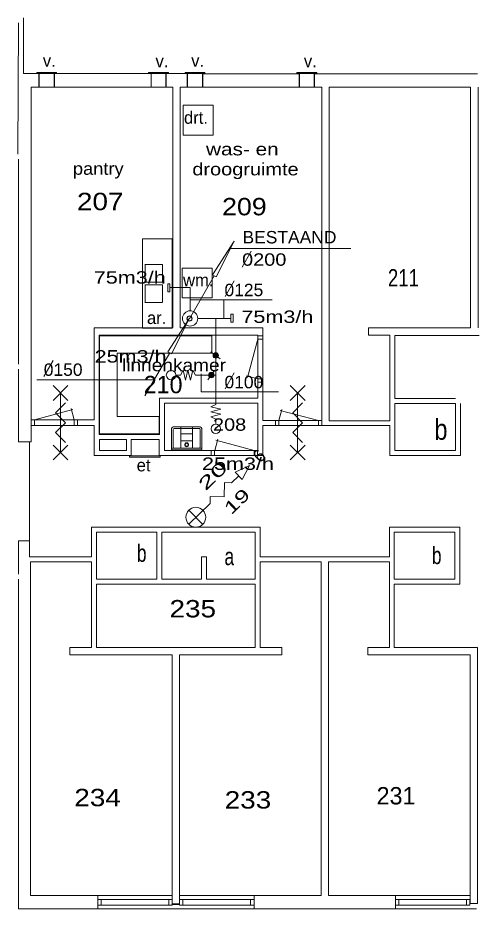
# Model space of a CAD drawing. Extents: x 295824 to 414724, y 24924 to 109024.
# Drawn here: x 361055 to 370346, y 62517 to 80477 of the extents above; entities that cross this region are included whole.
import ezdxf
from ezdxf.enums import TextEntityAlignment as Align

# ---------------------------------------------------------------- set-up
doc = ezdxf.new("R2010")
doc.units = 0
doc.header["$LTSCALE"] = 100
for name, color, linetype, lineweight in [('1', 7, 'Continuous', 13), ('24', 7, 'Continuous', 13), ('61', 7, 'Continuous', 13)]:
    doc.layers.add(name, color=color, linetype=linetype, lineweight=lineweight)

msp = doc.modelspace()

# ---------------------------------------------------------------- hatches: boundary and pattern name
at = {"layer": '24'}
for points in [[(364986.6, 73674.2, 1), (365095.2, 73674.2, 1)], [(364951.3, 73331.6, 1), (364951.3, 73223, 1)]]:
    msp.add_hatch(color=256, dxfattribs=at).paths.add_polyline_path(points)

# ---------------------------------------------------------------- linework, layer by layer
at = {"layer": '1'}
for p, q in [((364511.7, 74414.9), (365011.7, 75280.9)), ((363614.5, 72863.1), (364114.5, 73729.1))]:
    msp.add_line(p, q, dxfattribs=at)
for points in [[(365411.7, 75973.9), (365047.7, 75259.9), (364975.7, 75301.9)], [(364514.5, 74422.1), (364150.5, 73708.1), (364078.5, 73750.1)]]:
    msp.add_lwpolyline(points, close=True, dxfattribs=at)
msp.add_lwpolyline([(364526.2, 74579.8), (364526.2, 75046.4), (364118.1, 75046.4)], dxfattribs=at)
for centre in [(364511.6, 74414.6), (364514.5, 74421.8)]:
    msp.add_circle(centre, 50, dxfattribs=at)
at = {"layer": '24'}
for p, q in [((365322.8, 75827.7), (367762.3, 75827.7)), ((365757.4, 75774.7), (365573.1, 75455.4)), ((365413.1, 75178.3), (365228.7, 74859)), ((364526.2, 74795.5), (366180.1, 74795.5)), ((365205.3, 74433.6), (365205.3, 74795.5)), ((364678.1, 74419.5), (365340.7, 74419.5)), ((365040.9, 72738.8), (365040.9, 74419.5)), ((365132.5, 73603.3), (364941, 73745)), ((361763.6, 73571.9), (361579.3, 73252.6)), ((364880.5, 73185.7), (365022.2, 73377.3)), ((365413.1, 73321.7), (365228.7, 73002.3)), ((361439.1, 73184.3), (363799.9, 73184.3)), ((364682.2, 73277.3), (365040.9, 73277.3))]:
    msp.add_line(p, q, dxfattribs=at)
for points in [[(364116.5, 75115.3), (364073, 75115.3), (364073, 74953), (364116.5, 74953)], [(365390.7, 74507), (365347.2, 74507), (365347.2, 74344.7), (365390.7, 74344.7)]]:
    msp.add_lwpolyline(points, close=True, dxfattribs=at)
for points in [[(364232.2, 73277.3), (364332.2, 73277.3), (364382.2, 73377.3), (364432.2, 73177.3), (364482.2, 73377.3), (364532.2, 73177.3), (364582.2, 73377.3), (364632.2, 73277.3), (364682.2, 73277.3)], [(364749.3, 73300.7), (364749.3, 72938.9), (366305.9, 72938.9)], [(365040.9, 72288.8), (365040.9, 72388.8), (364940.9, 72438.8), (365140.9, 72488.8), (364940.9, 72538.8), (365140.9, 72588.8), (364940.9, 72638.8), (365040.9, 72688.8), (365040.9, 72738.8)]]:
    msp.add_lwpolyline(points, dxfattribs=at)
for centre, radius in [((364524.6, 74419.5), 153.6), ((365040.9, 73674.2), 54.3), ((364140.5, 73277.3), 95), ((364951.3, 73277.3), 54.3), ((365040.9, 72197.1), 95)]:
    msp.add_circle(centre, radius, dxfattribs=at)
at = {"layer": '61'}
for p, q in [((361168.1, 80477.2), (361168.1, 79352.1)), ((361055.1, 77727.2), (361068.1, 80377.2)), ((361168.1, 79352.1), (364468.2, 79352.1)), ((361833.8, 79372.3), (361435.5, 79372.3)), ((361435.5, 79372.3), (361435.5, 79357.2)), ((361833.8, 79357.2), (361435.5, 79357.2)), ((361480.2, 79352.1), (361480.2, 79082.1)), ((361485.8, 79357.2), (361485.8, 79082.8)), ((361784.5, 79357.2), (361784.5, 79082.8)), ((361790.9, 79350.8), (361790.9, 79082.3)), ((361833.8, 79372.3), (361833.8, 79357.2)), ((364087.5, 79372.3), (363689.2, 79372.3)), ((363689.2, 79372.3), (363689.2, 79357.2)), ((364087.5, 79357.2), (363689.2, 79357.2)), ((363739.5, 79357.2), (363739.5, 79082.8)), ((364038.2, 79357.2), (364038.2, 79082.8)), ((364044.6, 79350.7), (364044.6, 79080.7)), ((364087.5, 79372.3), (364087.5, 79357.2)), ((364821.8, 79372.3), (364423.5, 79372.3)), ((364423.5, 79372.3), (364423.5, 79357.2)), ((364821.8, 79357.2), (364423.5, 79357.2)), ((364468.2, 79352.1), (364468.2, 79082.1)), ((364473.7, 79357.2), (364473.7, 79082.8)), ((364772.4, 79357.2), (364772.4, 79082.8)), ((364778.9, 79350.8), (364778.9, 79082.3)), ((364778.9, 79350.8), (366721.9, 79350.8)), ((364821.8, 79372.3), (364821.8, 79357.2)), ((367075.5, 79372.3), (366677.2, 79372.3)), ((366677.2, 79372.3), (366677.2, 79357.2)), ((367075.5, 79357.2), (366677.2, 79357.2)), ((366721.9, 79350.8), (366721.9, 79082.3)), ((366727.5, 79357.2), (366727.5, 79082.8)), ((367026.2, 79357.2), (367026.2, 79082.8)), ((367032.6, 79350.7), (370310.6, 79350.7)), ((367032.6, 79350.7), (367032.6, 79080.7)), ((367075.5, 79372.3), (367075.5, 79357.2)), ((361325.1, 71936.1), (361325.1, 79080.7)), ((361784.5, 79082.8), (361485.8, 79082.8)), ((361790.9, 79082.3), (361936.7, 79082.3)), ((363587.2, 79082.3), (363733.9, 79082.3)), ((364038.2, 79082.8), (363739.5, 79082.8)), ((364325.1, 79082.1), (364468.2, 79082.1)), ((364325.1, 74230.7), (364325.1, 79080.8)), ((367175.1, 79080.8), (364325.1, 79080.8)), ((364772.4, 79082.8), (364473.7, 79082.8)), ((364778.9, 79082.3), (364924.7, 79082.3)), ((366575.2, 79082.3), (366721.9, 79082.3)), ((367026.2, 79082.8), (366727.5, 79082.8)), ((367032.6, 79080.7), (367175.1, 79080.7)), ((367175.1, 72262), (367175.1, 79080.8)), ((370325.1, 79080.7), (370325.1, 74230.7)), ((361068.1, 77627.2), (361068.1, 73497.4)), ((363615.5, 75505.1), (363965.5, 75505.1)), ((363966.4, 75503.5), (363966.4, 75153.5)), ((363965.5, 75151), (363615.5, 75151)), ((363615.5, 75096.9), (363965.5, 75096.9)), ((363966.4, 75095.3), (363966.4, 74745.3)), ((363965.5, 74742.8), (363615.5, 74742.8)), ((362590.4, 74230.7), (362590.4, 72374.6)), ((364325.1, 74230.7), (365990.4, 74230.7)), ((362690.4, 72080.4), (362690.4, 74085.4)), ((365888.4, 74001.2), (365681.4, 73228.4)), ((365989.9, 74067.4), (365889, 74067.4)), ((365987.9, 74000.4), (365890.4, 74000.4)), ((365988.3, 74067.4), (365891.6, 74067.4)), ((368650.1, 72805.7), (368650.1, 74079.4)), ((370346.5, 74079.4), (368650.1, 74079.4)), ((365887.8, 73202.8), (365660.9, 73263.5)), ((365987.7, 73200.4), (365889, 73200.4)), ((365987.9, 73133.4), (365889, 73133.4)), ((362063.4, 73069.3), (361763.4, 72769.3)), ((361763.4, 73069.3), (362063.4, 72769.3)), ((361913.4, 71719.3), (361913.4, 72919.3)), ((366840.6, 73069.3), (366540.6, 72769.3)), ((366540.6, 73069.3), (366840.6, 72769.3)), ((366690.6, 71719.3), (366690.6, 72919.3)), ((368650.1, 72805.7), (369870.1, 72805.7)), ((361392, 72375.2), (362164.8, 72582.3)), ((362190.5, 72375.9), (362129.7, 72602.7)), ((366311.1, 72361.5), (366371.9, 72588.4)), ((367109.5, 72360.9), (366336.8, 72567.9)), ((369970.1, 71655.7), (369970.1, 72705.7)), ((361392.8, 72260.6), (361392.8, 72374.6)), ((362192.8, 72260.6), (362192.8, 72374.6)), ((362259.8, 72260.6), (362259.8, 72374.6)), ((362590.4, 71660.4), (362590.4, 72260.6)), ((364725.7, 72234.2), (364185.7, 72234.2)), ((364335.7, 71809.2), (364335.7, 72234.2)), ((364575.7, 71809.2), (364575.7, 72234.2)), ((365990.4, 72262), (367178.7, 72262)), ((365990.4, 72260.4), (365990.4, 71660.4)), ((366241.8, 72261.4), (366241.8, 72360.3)), ((366308.8, 72261.6), (366308.8, 72360.3)), ((367108.8, 72261.4), (367108.8, 72360.3)), ((367175.1, 72262), (368550.1, 72262)), ((367175.8, 72262), (367175.8, 72360.4)), ((368550.1, 71655.7), (368550.1, 72262)), ((363910.4, 72080.4), (362690.4, 72080.4)), ((364150.7, 72199.2), (364150.7, 71784.2)), ((364185.7, 71824.2), (364185.7, 72184.2)), ((364200.7, 72199.2), (364710.7, 72199.2)), ((364575.7, 72092.5), (364335.7, 72092.5)), ((364725.7, 72184.2), (364725.7, 71824.2)), ((364760.7, 71784.2), (364760.7, 72199.2)), ((361288.1, 71936.1), (361288.1, 69616.5)), ((362063.4, 71869.3), (361763.4, 71569.3)), ((361763.4, 71869.3), (362063.4, 71569.3)), ((362700.4, 71760.4), (362700.4, 71980.4)), ((363240.4, 71980.4), (362700.4, 71980.4)), ((363240.4, 71760.4), (363240.4, 71980.4)), ((363340.4, 71660.4), (363340.4, 71980.4)), ((363900.4, 71980.4), (363340.4, 71980.4)), ((363900.4, 71660.4), (363900.4, 71980.4)), ((364575.7, 71950.8), (364335.7, 71950.8)), ((365019.8, 71760.5), (365080.6, 71987.4)), ((365818.2, 71759.9), (365045.5, 71966.9)), ((366840.6, 71869.3), (366540.6, 71569.3)), ((366540.6, 71869.3), (366840.6, 71569.3)), ((363240.4, 71760.4), (362700.4, 71760.4)), ((364750.7, 71809.2), (364160.7, 71809.2)), ((364160.7, 71774.2), (364750.7, 71774.2)), ((364950.5, 71660.4), (364950.5, 71759.3)), ((365017.5, 71660.6), (365017.5, 71759.3)), ((365817.5, 71660.4), (365817.5, 71759.3)), ((365884.5, 71660.4), (365884.5, 71759.3)), ((363340.4, 71660.4), (362590.4, 71660.4)), ((363306.2, 71653.3), (363924.6, 71653.3)), ((363306.2, 71625.6), (363306.2, 71653.3)), ((365990.4, 71660.4), (363900.4, 71660.4)), ((369970.1, 71655.7), (368550.1, 71655.7)), ((364501.1, 70558.2), (364779, 70270.4)), ((362537.4, 70216.5), (362537.4, 69616.5)), ((365937.4, 70216.5), (362537.4, 70216.5)), ((365937.4, 69616.5), (365937.4, 70216.5)), ((369957.4, 70216.5), (369957.4, 69066.5)), ((362537.4, 69616.5), (361288.1, 69616.5)), ((361068.1, 69167.6), (361068.1, 62521.5)), ((368637.4, 69066.5), (368637.4, 67791.9)), ((368637.4, 69066.5), (369957.4, 69066.5)), ((370312.4, 67791.9), (368637.4, 67791.9)), ((370312.4, 62630.9), (370312.4, 67791.9)), ((361312.4, 62791.5), (364162.4, 62791.5)), ((362663.7, 62516.8), (362663.7, 62786.8)), ((362730.4, 62595.1), (362730.4, 62709)), ((364095.4, 62594.5), (364095.4, 62708.5)), ((367162.4, 62791.5), (364312.4, 62791.5)), ((364378.9, 62595.5), (364378.9, 62709.5)), ((365743.2, 62595.2), (365743.2, 62708.8)), ((365811.7, 62516.8), (365811.7, 62787)), ((367312.4, 62791.5), (370162.4, 62791.5)), ((368660.5, 62519.4), (368660.5, 62789.4)), ((368727.3, 62595.1), (368727.3, 62709)), ((370092.3, 62594.5), (370092.3, 62708.5)), ((361068.1, 62521.5), (370292.2, 62521.5)), ((364162.4, 62624.5), (364312.4, 62624.5)), ((364162.4, 62609.5), (364312.4, 62609.5)), ((370160.9, 62630.9), (370312.4, 62630.9))]:
    msp.add_line(p, q, dxfattribs=at)
for points in [[(361325.1, 79080.7), (364175.1, 79080.7), (364175.1, 74230.7), (362590.4, 74230.7)], [(363567.3, 74225.2), (364162, 74225.2), (364162, 76025.2)], [(363567.3, 74225.2), (363567.3, 76025.2), (364162, 76025.2)], [(363616.4, 75153.5), (363616.4, 75503.5), (363615.5, 75505.1)], [(363616.4, 74745.3), (363616.4, 75095.3), (363615.5, 75096.9)], [(365990.4, 74230.7), (365990.4, 72360.4), (367175.8, 72360.4)], [(362690.4, 74085.4), (365890.4, 74085.4), (365890.4, 72810.4), (363910.4, 72810.4), (363910.4, 72080.4)], [(361068.1, 73397.4), (361068.1, 71936.1), (361325.1, 71936.1)], [(362013.4, 71919.3), (361813.4, 72119.3), (362013.4, 72319.3), (361813.4, 72519.3), (362013.4, 72719.3)], [(366790.6, 71919.3), (366590.6, 72119.3), (366790.6, 72319.3), (366590.6, 72519.3), (366790.6, 72719.3)], [(361325.8, 72260.6), (361325.8, 72374.6), (362590.4, 72374.6)], [(362590.4, 72260.6), (361325.8, 72260.6), (361325.8, 72374.6)], [(363306.2, 71625.6), (363924.6, 71625.6), (363924.6, 71653.3)], [(364496.2, 70275.4), (364927.8, 70692.2), (364930.2, 70833.6), (365213, 70828.6), (365218, 71111.4), (365359.4, 71109), (365503.2, 71247.9)], [(369957.4, 70216.5), (368537.4, 70216.5), (368537.4, 69616.5)], [(361288.1, 69936.1), (361068.1, 69936.1), (361068.1, 69267.6)], [(364162.4, 62609.5), (364162.4, 67641.5), (362102.4, 67641.5), (362102.4, 67791.5), (362537.4, 67791.5), (362537.4, 69516.5), (361312.4, 69516.5), (361312.4, 62791.5)], [(364312.4, 62609.5), (364312.4, 67641.5), (366372.4, 67641.5), (366372.4, 67791.5), (365937.4, 67791.5), (365937.4, 69516.5), (367162.4, 69516.5), (367162.4, 62791.5)], [(365937.4, 69616.5), (368537.4, 69616.5), (367312.4, 69616.5)], [(370162.4, 62630.9), (370162.4, 67641.5), (368102.4, 67641.5), (368102.4, 67791.5), (368537.4, 67791.5), (368537.4, 69516.5), (367312.4, 69516.5), (367312.4, 62791.5)]]:
    msp.add_lwpolyline(points, dxfattribs=at)
for points in [[(367325.1, 79080.7), (370175.1, 79080.7), (370175.1, 74230.7), (368115.1, 74230.7), (368115.1, 74080.7), (368550.1, 74080.7), (368550.1, 72355.7), (367325.1, 72355.7)], [(364382.4, 78115.6), (364382.4, 78715.6), (364986.8, 78715.6), (364986.8, 78115.6)], [(364362.7, 74835.5), (364362.7, 75435.5), (364967.2, 75435.5), (364967.2, 74835.5)], [(362712.9, 74070.1), (364960.1, 74070.1), (364960.1, 73720.1), (363054.4, 73720.1), (363054.4, 72442.9), (363902.1, 72442.9), (363902.1, 72092.9), (362700.6, 72092.9), (362700.6, 74070.1)], [(364010.4, 72710.4), (365890.4, 72710.4), (365890.4, 71760.4), (364010.4, 71760.4)], [(368650.1, 72705.7), (369870.1, 72705.7), (369870.1, 71755.7), (368650.1, 71755.7)], [(365572.7, 71176), (365433.8, 71319.8), (365719, 71456.3)], [(362637.4, 69166.5), (363857.4, 69166.5), (363857.4, 70116.5), (362637.4, 70116.5)], [(363957.4, 69166.5), (364757.4, 69166.5), (364757.4, 69616.5), (364857.4, 69616.5), (364857.4, 69166.5), (365837.4, 69166.5), (365837.4, 70116.5), (363957.4, 70116.5)], [(368637.4, 69166.5), (369857.4, 69166.5), (369857.4, 70116.5), (368637.4, 70116.5)], [(362637.4, 67791.5), (365837.4, 67791.5), (365837.4, 69066.5), (362637.4, 69066.5)], [(362663.6, 62595), (362663.6, 62709), (364162.2, 62709), (364162.2, 62595)], [(364312.6, 62595.2), (364312.6, 62709.2), (365812, 62709.2), (365812, 62595.2)], [(368660.5, 62595), (368660.5, 62709), (370159.1, 62709), (370159.1, 62595)]]:
    msp.add_lwpolyline(points, close=True, dxfattribs=at)
for centre, radius in [((364455.7, 71874.2), 40), ((364455.7, 71874.2), 30), ((364640, 70414.3), 200)]:
    msp.add_circle(centre, radius, dxfattribs=at)
for centre, radius, start, end in [((364185.7, 72199.2), 35, 90, 180), ((364725.7, 72199.2), 35, 0, 90), ((364200.7, 72184.2), 15, 90, 180), ((364710.7, 72184.2), 15, 0, 90), ((364160.7, 71799.2), 10, 90, 180), ((364160.7, 71784.2), 10, 180, 270), ((364200.7, 71824.2), 15, 180, 270), ((364710.7, 71824.2), 15, 270, 0), ((364750.7, 71799.2), 10, 0, 90), ((364750.7, 71784.2), 10, 270, 0)]:
    msp.add_arc(centre, radius, start, end, dxfattribs=at)

# ---------------------------------------------------------------- texts
at = {"layer": '24'}
for s, width, p in [('BESTAAND', 1.05, (365580.2, 75931.8)), ('0200', 1.2, (365571.3, 75481.8)), ('75m3/h', 1.3, (362584.5, 75121.3)), ('0125', 1.05, (365217.3, 74868.6)), ('75m3/h', 1.3, (365557.7, 74329.7)), ('25m3/h', 1.3, (362601.4, 73530.7)), ('0150', 1.05, (361577.5, 73263.2)), ('0100', 1.05, (365217.3, 73011.9)), ('25m3/h', 1.3, (364764.1, 71368))]:
    msp.add_text(s, height=250, dxfattribs=dict(at, width=width)).set_placement(p)
at = {"layer": '61'}
for s, p in [('v.', (361558.8, 79490.7)), ('v.', (363828, 79480.6)), ('v.', (364546.8, 79490.7)), ('v.', (366816, 79480.6)), ('drt.', (364402, 78341.8)), ('wm.', (364382.4, 75069.1)), ('ar.', (363655.8, 74307.5)), ('et', (363448.7, 71338.4))]:
    msp.add_text(s, height=250, dxfattribs=at).set_placement(p)
for s, width, p in [('was- en', 1.25, (364845.2, 77706.1)), ('pantry', 1.1, (362164.2, 77314.1)), ('droogruimte', 1.2, (364569.9, 77302.8)), ('linnenkamer', 1.15, (363153.4, 73355.2))]:
    msp.add_text(s, height=250, dxfattribs=dict(at, width=width)).set_placement(p)
for s, height, width, p in [('207', 350, 1.2, (362714.5, 76601.4)), ('209', 350, 1.15, (365618.3, 76497.7)), ('211', 350, 0.8, (368821.1, 75063.9)), ('208', 250, 1.2, (365319.7, 72156.8)), ('b', 420, 0.85, (369576.3, 71973.7)), ('b', 350, 0.75, (363549.6, 69514.7)), ('a', 350, 0.75, (365314.4, 69448.8)), ('b', 350, 0.75, (369491.2, 69469.2)), ('235', 350, 1.2, (364578.5, 68395.9)), ('234', 350, 1.2, (362661.4, 64591.3)), ('233', 350, 1.2, (365690.3, 64544.1))]:
    msp.add_text(s, height=height, dxfattribs=dict(at, width=width)).set_placement(p, align=Align.CENTER)
for s, p in [('210', (363981.1, 72913.1)), ('231', (368671.7, 64627.1))]:
    msp.add_text(s, height=350, dxfattribs=at).set_placement(p, align=Align.CENTER)
msp.add_text('6', height=250, rotation=44, dxfattribs=at).set_placement((365934.3, 71498.4))
for s, width, p in [('20', 1.75, (364834.3, 70933.5)), ('19', 1.5, (365354.5, 70452.1))]:
    msp.add_text(s, height=250, rotation=44, dxfattribs=dict(at, width=width)).set_placement(p)

doc.saveas('drawing.dxf')
